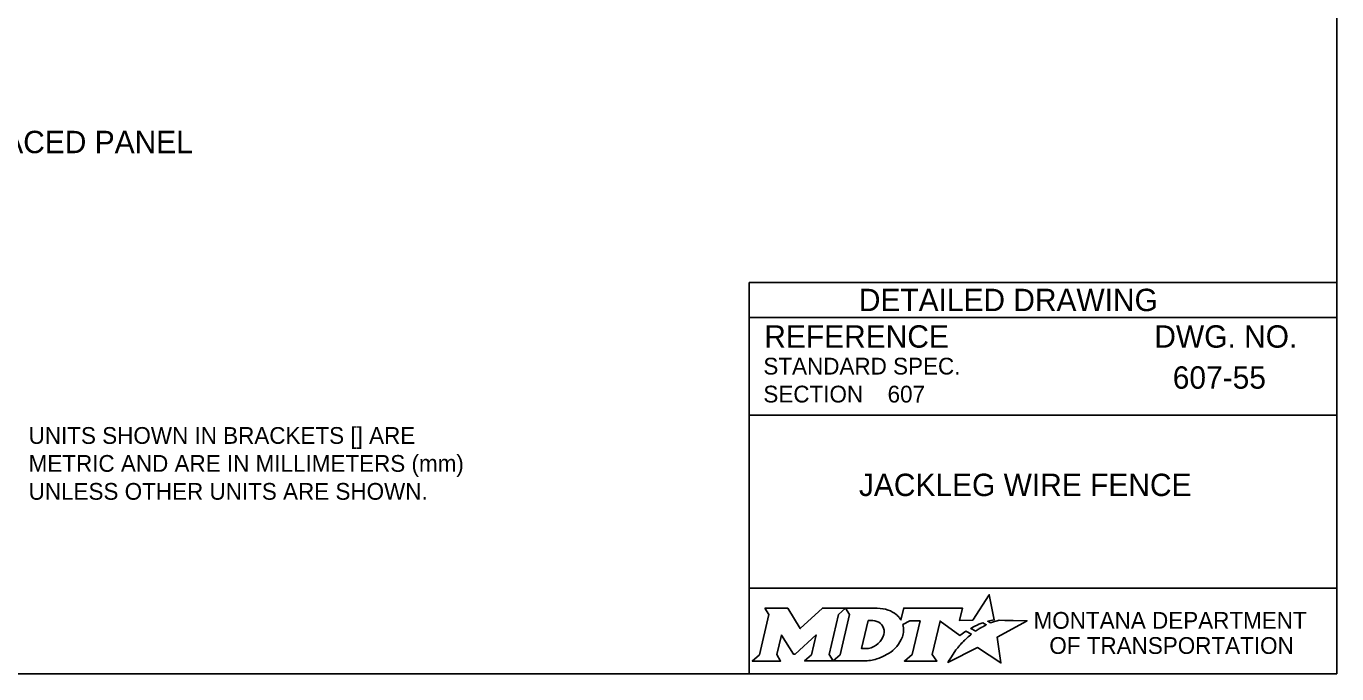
# Model space of a CAD drawing. Extents: x 49991.4 to 50021, y 49987.6 to 50011.4.
# Drawn here: x 50012.065 to 50016.75, y 49987.799 to 49990.115 of the extents above; entities that cross this region are included whole.
import ezdxf

# ---------------------------------------------------------------- set-up
doc = ezdxf.new("R2010")
doc.units = 0
for name, color, linetype in [('Default', 7, 'Continuous'), ('Level 1', 7, 'Continuous'), ('Level 2', 7, 'Continuous'), ('Level 3', 7, 'Continuous'), ('Level 5', 7, 'Continuous')]:
    doc.layers.add(name, color=color, linetype=linetype)

msp = doc.modelspace()

# ---------------------------------------------------------------- linework, layer by layer
at = {"layer": 'Default'}
for points in [[(50015.5126, 49987.9811), (50015.5023, 49987.9867), (50015.5139, 49987.9895), (50015.5255, 49987.9915), (50015.5081, 49988.0816), (50015.4486, 49987.9903), (50015.4013, 49987.9896), (50015.4116, 49988.0337), (50015.2024, 49988.0338), (50015.1923, 49987.9913), (50015.1865, 49987.9996)], [(50014.7056, 49988.0338), (50014.7197, 49988.0104), (50014.6862, 49987.8671), (50014.6605, 49987.8446), (50014.7621, 49987.8446), (50014.7486, 49987.8674), (50014.7648, 49987.9375), (50014.8085, 49987.8685), (50014.8138, 49987.8685), (50014.8889, 49987.938), (50014.8725, 49987.8669), (50014.8478, 49987.8449), (50014.9494, 49987.8449), (50014.9356, 49987.8682), (50014.9688, 49988.0106)], [(50014.9688, 49988.0106), (50014.9941, 49988.0338), (50014.9117, 49988.0338), (50014.8321, 49987.9608), (50014.7876, 49988.0335), (50014.7056, 49988.0338)], [(50015.1077, 49988.0338), (50014.9941, 49988.0338), (50015.0088, 49988.0109), (50014.9749, 49987.8671), (50014.9494, 49987.8449), (50015.06, 49987.8449)], [(50015.1317, 49987.9471), (50015.1305, 49987.939), (50015.1273, 49987.9297), (50015.1231, 49987.9215), (50015.1175, 49987.914), (50015.111, 49987.9071), (50015.1031, 49987.9008), (50015.0948, 49987.8961), (50015.0857, 49987.8922), (50015.0766, 49987.8899), (50015.0674, 49987.889), (50015.0515, 49987.889), (50015.0751, 49987.989), (50015.0911, 49987.989), (50015.0987, 49987.9884), (50015.1063, 49987.9865), (50015.1129, 49987.9835), (50015.119, 49987.9793), (50015.1238, 49987.9743), (50015.1275, 49987.9683), (50015.1302, 49987.9621), (50015.1318, 49987.9547), (50015.1318, 49987.9517), (50015.1317, 49987.9471)], [(50015.1991, 49987.9747), (50015.2237, 49987.9878), (50015.2606, 49987.9878), (50015.232, 49987.8673), (50015.2045, 49987.8446), (50015.3207, 49987.8446), (50015.3037, 49987.8675), (50015.3319, 49987.9877), (50015.4032, 49987.936), (50015.4243, 49987.9511), (50015.444, 49987.9402)], [(50015.3882, 49987.8843), (50015.3729, 49987.8599), (50015.3682, 49987.8524), (50015.3624, 49987.8438), (50015.3601, 49987.8395), (50015.4654, 49987.8926), (50015.5493, 49987.8375), (50015.5362, 49987.9302), (50015.6431, 49987.9886), (50015.5938, 49987.9894), (50015.5637, 49987.9898), (50015.5429, 49987.9901), (50015.5361, 49987.9886), (50015.5312, 49987.9874), (50015.5228, 49987.9851), (50015.5126, 49987.9811)], [(50015.4622, 49987.9535), (50015.4598, 49987.9518), (50015.4415, 49987.9614), (50015.4518, 49987.9671), (50015.4559, 49987.9693), (50015.4645, 49987.9733), (50015.4702, 49987.9759), (50015.4781, 49987.9789), (50015.4854, 49987.9816), (50015.4972, 49987.9742), (50015.4932, 49987.9721), (50015.4886, 49987.9696), (50015.4844, 49987.9674), (50015.4794, 49987.9645), (50015.4775, 49987.9634), (50015.4748, 49987.9618), (50015.4723, 49987.9604), (50015.47, 49987.9588), (50015.4674, 49987.957), (50015.4647, 49987.9552), (50015.4622, 49987.9535)], [(50015.4021, 49987.9004), (50015.4021, 49987.9004)], [(50015.1057, 49987.8522), (50015.1141, 49987.8548), (50015.1271, 49987.8602), (50015.1475, 49987.8712)]]:
    msp.add_lwpolyline(points, dxfattribs=at)
for centre, radius, start, end in [((50015.1308, 49987.9554), 0.0709, 339.5329, 15.8582), ((50015.0868, 49987.9727), 0.1183, 300.9103, 339.1383)]:
    msp.add_arc(centre, radius, start, end, dxfattribs=at)
for centre, major_axis, ratio, start_param, end_param in [((50015.1056, 49987.9864), (0.0834, -0.0037), 0.568097, 0.61298, 1.570796), ((50015.1612, 49987.9937), (0.0361, -0.0295), 0.469099, 1.225588, 1.570796), ((50015.4119, 49987.9106), (-0.0098, -0.0102), 0.016458, 3.141593, 6.279097), ((50015.4329, 49987.9305), (-0.0112, -0.0097), 0.021651, 3.157348, 6.283185), ((50015.3952, 49987.8923), (-0.00694, -0.00806), 0.008222, 0, 3.137361), ((50015.0603, 49987.9932), (0, 0.1484), 0.987302, 3.139398, 3.456847)]:
    msp.add_ellipse(centre, major_axis=major_axis, ratio=ratio, start_param=start_param, end_param=end_param, dxfattribs=at)
at = {"layer": 'Level 1'}
msp.add_lwpolyline([(49999.3835, 49998.9992), (50016.7501, 49998.9992), (50016.7501, 49987.7988), (49999.3835, 49987.7988)], close=True, dxfattribs=at)
at = {"layer": 'Level 3'}
msp.add_line((49999.3835, 49987.7988), (50016.7501, 49987.7988), dxfattribs=at)
at = {"layer": 'Level 5'}
for p, q in [((50016.7501, 49989.1988), (50014.6501, 49989.1988)), ((50014.6501, 49989.1988), (50014.6501, 49987.7988)), ((50016.7501, 49989.0738), (50014.6501, 49989.0738)), ((50016.3862, 49988.8587), (50016.3862, 49988.8587)), ((50015.1444, 49988.7993), (50015.1444, 49988.7993)), ((50016.7501, 49988.7238), (50014.6501, 49988.7238)), ((50015.7001, 49988.4747), (50015.7001, 49988.4747)), ((50016.7501, 49988.1057), (50014.6501, 49988.1057))]:
    msp.add_line(p, q, dxfattribs=at)

# ---------------------------------------------------------------- texts
at = {"layer": 'Default'}
for s, p in [('MONTANA DEPARTMENT', (50015.6663, 49987.96)), ('OF TRANSPORTATION', (50015.7225, 49987.87))]:
    msp.add_text(s, height=0.06, dxfattribs=at).set_placement(p)
at = {"layer": 'Level 2'}
for s, height, p in [('BRACED PANEL', 0.08, (50011.8347, 49989.6612)), ('607-55', 0.08, (50016.1637, 49988.8187)), ('607', 0.06, (50015.1444, 49988.7693)), ('UNITS SHOWN IN BRACKETS [] ARE ', 0.06, (50012.074, 49988.6214)), ('METRIC AND ARE IN MILLIMETERS (mm) ', 0.06, (50012.074, 49988.5214)), ('JACKLEG WIRE FENCE', 0.08, (50015.042, 49988.4347)), ('UNLESS OTHER UNITS ARE SHOWN.', 0.06, (50012.074, 49988.4214))]:
    msp.add_text(s, height=height, dxfattribs=at).set_placement(p)
at = {"layer": 'Level 5'}
for s, height, p in [('DETAILED DRAWING', 0.0799, (50015.0418, 49989.0963)), ('REFERENCE', 0.08, (50014.7037, 49988.9654)), ('DWG. NO.', 0.08, (50016.0979, 49988.9654)), ('STANDARD SPEC.', 0.06, (50014.7004, 49988.8694)), ('SECTION', 0.06, (50014.7004, 49988.7694))]:
    msp.add_text(s, height=height, dxfattribs=at).set_placement(p)

doc.saveas('drawing.dxf')
